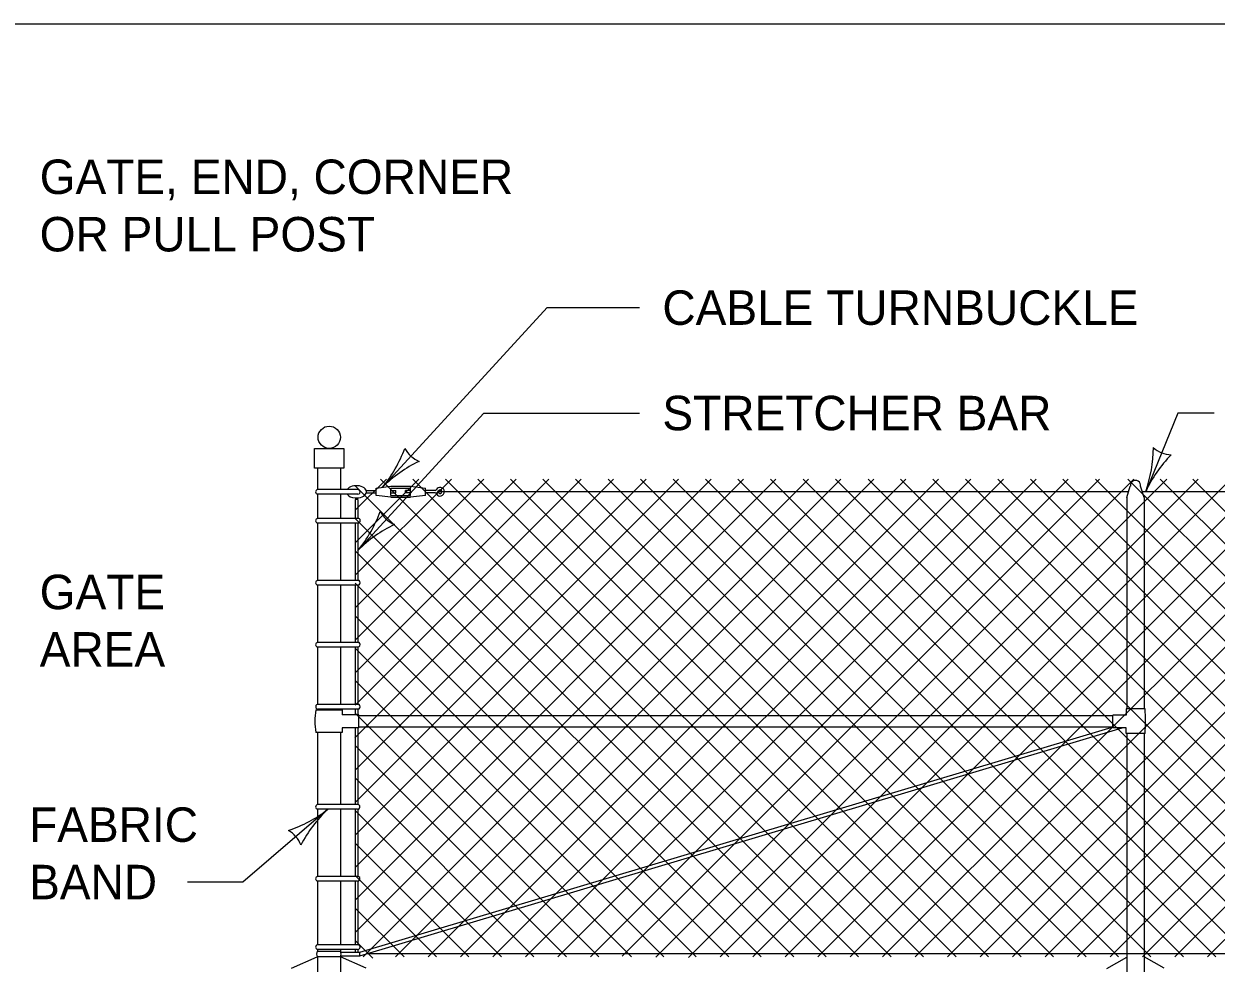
# Model space of a CAD drawing. Extents: x 49973.1 to 50021, y 49987.6 to 50015.4.
# Drawn here: x 50004.917 to 50006.994, y 49997.363 to 49998.999 of the extents above; entities that cross this region are included whole.
import ezdxf

# ---------------------------------------------------------------- set-up
doc = ezdxf.new("R2010")
doc.units = 0
for name, color, linetype in [('Level 1', 7, 'Continuous'), ('Level 2', 7, 'Continuous'), ('Level 3', 7, 'Continuous')]:
    doc.layers.add(name, color=color, linetype=linetype)

msp = doc.modelspace()

# ---------------------------------------------------------------- linework, layer by layer
at = {"layer": 'Level 1'}
for p, q in [((50005.4288, 49998.2252), (50005.4288, 49998.188)), ((50005.4688, 49998.2252), (50005.4688, 49998.188)), ((50005.9448, 49998.2062), (50005.4942, 49997.7556)), ((50005.5489, 49998.2062), (50005.4944, 49998.1518)), ((50005.6055, 49998.2062), (50005.4944, 49998.0952)), ((50005.6621, 49998.2062), (50005.4944, 49998.0386)), ((50005.7187, 49998.2062), (50005.4944, 49997.9819)), ((50005.8317, 49998.2062), (50005.4944, 49997.8689)), ((50005.7751, 49998.2062), (50005.4944, 49997.9255)), ((50005.8885, 49998.2062), (50005.4944, 49997.8124)), ((50006.2842, 49998.2062), (50005.4944, 49997.4164)), ((50006.1711, 49998.2062), (50005.4944, 49997.5295)), ((50006.1147, 49998.2062), (50005.4944, 49997.5859)), ((50006.058, 49998.2062), (50005.4944, 49997.6426)), ((50006.0015, 49998.2062), (50005.4944, 49997.6991)), ((50006.2276, 49998.2062), (50005.4944, 49997.473)), ((50006.3152, 49997.3739), (50005.4944, 49998.1947)), ((50006.3408, 49998.2062), (50005.5084, 49997.3738)), ((50005.531, 49998.1906), (50005.5568, 49998.1938)), ((50006.3716, 49997.3739), (50005.5389, 49998.2062)), ((50005.5568, 49998.1938), (50005.591, 49998.1938)), ((50006.3978, 49998.2062), (50005.565, 49997.3738)), ((50005.591, 49998.1938), (50005.6168, 49998.1906)), ((50006.4282, 49997.3739), (50005.5953, 49998.2062)), ((50006.454, 49998.2062), (50005.6216, 49997.3738)), ((50006.4848, 49997.3739), (50005.6521, 49998.2062)), ((50006.5104, 49998.2062), (50005.678, 49997.3738)), ((50006.5414, 49997.3739), (50005.7083, 49998.2062)), ((50006.567, 49998.2062), (50005.7346, 49997.3738)), ((50006.5978, 49997.3739), (50005.765, 49998.2062)), ((50006.624, 49998.2062), (50005.7912, 49997.3738)), ((50006.6544, 49997.3739), (50005.8217, 49998.2062)), ((50006.6806, 49998.2062), (50005.8478, 49997.3738)), ((50006.711, 49997.3739), (50005.8786, 49998.2062)), ((50006.7368, 49998.2062), (50005.9044, 49997.3738)), ((50006.7676, 49997.3739), (50005.935, 49998.2062)), ((50006.791, 49998.2062), (50005.9598, 49997.375)), ((50006.8242, 49997.3739), (50005.9917, 49998.2062)), ((50006.8511, 49998.2062), (50006.0181, 49997.3733)), ((50006.8808, 49997.3739), (50006.0484, 49998.2062)), ((50006.9085, 49998.2062), (50006.075, 49997.3728)), ((50006.9375, 49997.3738), (50006.1047, 49998.2062)), ((50006.9631, 49998.2062), (50006.1306, 49997.3738)), ((50006.9939, 49997.3738), (50006.1614, 49998.2062)), ((50007.0197, 49998.2062), (50006.1872, 49997.3738)), ((50007.0505, 49997.3738), (50006.218, 49998.2062)), ((50007.0763, 49998.2062), (50006.2438, 49997.3738)), ((50007.1071, 49997.3738), (50006.2747, 49998.2062)), ((50007.1329, 49998.2062), (50006.3004, 49997.3738)), ((50007.1637, 49997.3738), (50006.3313, 49998.2062)), ((50007.1895, 49998.2062), (50006.357, 49997.3738)), ((50007.2203, 49997.3738), (50006.3879, 49998.2062)), ((50007.2459, 49998.2062), (50006.4134, 49997.3738)), ((50007.2769, 49997.3738), (50006.4445, 49998.2062)), ((50007.3025, 49998.2062), (50006.47, 49997.3738)), ((50007.2938, 49997.4132), (50006.5009, 49998.2062)), ((50007.2938, 49997.4698), (50006.5575, 49998.2062)), ((50007.2938, 49997.5264), (50006.6141, 49998.2062)), ((50007.2938, 49997.583), (50006.6707, 49998.2062)), ((50007.2938, 49997.6396), (50006.7273, 49998.2062)), ((50007.2938, 49997.6962), (50006.7839, 49998.2062)), ((50006.8388, 49998.1741), (50006.8448, 49998.1939)), ((50007.2938, 49997.7528), (50006.8405, 49998.2062)), ((50006.8688, 49998.1741), (50006.8625, 49998.1936)), ((50007.2938, 49997.8092), (50006.8969, 49998.2062)), ((50007.2938, 49997.8658), (50006.9535, 49998.2062)), ((50005.4994, 49998.188), (50005.4288, 49998.188)), ((50005.4288, 49998.18), (50005.4288, 49998.1378)), ((50005.4994, 49998.1799), (50005.429, 49998.1799)), ((50005.4688, 49998.1799), (50005.4688, 49998.1378)), ((50005.4994, 49998.1704), (50005.4944, 49998.1704)), ((50005.4944, 49998.1704), (50005.4944, 49998.1509)), ((50005.4994, 49998.1704), (50005.4994, 49998.1378)), ((50005.514, 49998.1863), (50005.531, 49998.1863)), ((50005.514, 49998.1821), (50005.531, 49998.1821)), ((50005.531, 49998.1778), (50005.531, 49998.1906)), ((50005.5568, 49998.1746), (50005.531, 49998.1778)), ((50005.5568, 49998.1906), (50005.591, 49998.1906)), ((50005.5568, 49998.1778), (50005.5568, 49998.1906)), ((50005.5568, 49998.1863), (50005.5653, 49998.1863)), ((50005.5568, 49998.1821), (50005.5653, 49998.1821)), ((50005.5568, 49998.1778), (50005.591, 49998.1778)), ((50005.5568, 49998.1746), (50005.591, 49998.1746)), ((50005.5653, 49998.1821), (50005.5653, 49998.1863)), ((50005.5825, 49998.1821), (50005.5825, 49998.1863)), ((50005.591, 49998.1863), (50005.5825, 49998.1863)), ((50005.591, 49998.1821), (50005.5825, 49998.1821)), ((50005.591, 49998.1778), (50005.591, 49998.1906)), ((50005.6168, 49998.1778), (50005.591, 49998.1746)), ((50005.6168, 49998.1778), (50005.6168, 49998.1906)), ((50005.6339, 49998.1863), (50005.6168, 49998.1863)), ((50005.6339, 49998.1821), (50005.6168, 49998.1821)), ((50005.6398, 49998.1826), (50005.6361, 49998.1804)), ((50006.8418, 49998.1843), (50005.6416, 49998.1843)), ((50006.8388, 49998.1741), (50006.8388, 49997.8059)), ((50007.2954, 49998.1843), (50006.8655, 49998.1843)), ((50006.8688, 49998.1741), (50006.8688, 49997.8059)), ((50005.4944, 49998.1509), (50005.4944, 49998.1378)), ((50005.4993, 49998.1378), (50005.4288, 49998.1378)), ((50005.4288, 49998.1298), (50005.4288, 49998.0298)), ((50005.4997, 49998.1297), (50005.429, 49998.1297)), ((50005.4688, 49998.1297), (50005.4688, 49998.0298)), ((50006.2586, 49997.3739), (50005.4944, 49998.1378)), ((50005.4944, 49998.1297), (50005.4944, 49998.0298)), ((50005.4994, 49998.1297), (50005.4994, 49998.0298)), ((50007.2938, 49998.141), (50006.5266, 49997.3738)), ((50006.202, 49997.3739), (50005.4944, 49998.0812)), ((50007.2938, 49998.0843), (50006.5832, 49997.3738)), ((50005.4993, 49998.0298), (50005.4288, 49998.0298)), ((50006.1454, 49997.3739), (50005.4944, 49998.0247)), ((50007.2938, 49998.0277), (50006.6398, 49997.3738)), ((50005.4288, 49998.0218), (50005.4288, 49997.9218)), ((50005.4992, 49998.0217), (50005.429, 49998.0217)), ((50005.4688, 49998.0217), (50005.4688, 49997.9218)), ((50005.4944, 49998.0217), (50005.4944, 49997.9218)), ((50005.4994, 49998.0217), (50005.4994, 49997.9218)), ((50006.0888, 49997.3739), (50005.4944, 49997.968)), ((50007.2938, 49997.9711), (50006.6964, 49997.3738)), ((50005.4993, 49997.9218), (50005.4288, 49997.9218)), ((50005.4288, 49997.9138), (50005.4288, 49997.8138)), ((50005.4992, 49997.9137), (50005.429, 49997.9137)), ((50005.4688, 49997.9137), (50005.4688, 49997.8138)), ((50005.4944, 49997.9137), (50005.4944, 49997.8138)), ((50006.0322, 49997.3739), (50005.4944, 49997.9117)), ((50005.4994, 49997.9137), (50005.4994, 49997.8138)), ((50007.2938, 49997.9147), (50006.7528, 49997.3738)), ((50005.9758, 49997.3739), (50005.4944, 49997.8551)), ((50007.2938, 49997.8581), (50006.8094, 49997.3738)), ((50005.4993, 49997.8138), (50005.4285, 49997.8138)), ((50005.4288, 49997.8059), (50005.4288, 49997.804)), ((50005.4992, 49997.8057), (50005.4299, 49997.8057)), ((50005.4688, 49997.8057), (50005.4688, 49997.804)), ((50005.4944, 49997.8057), (50005.4944, 49997.7956)), ((50005.9192, 49997.3739), (50005.4944, 49997.7987)), ((50005.4994, 49997.8057), (50005.4994, 49997.7956)), ((50006.8704, 49997.8059), (50006.8376, 49997.8059)), ((50006.8376, 49997.8059), (50006.8376, 49997.7951)), ((50007.2938, 49997.8015), (50006.866, 49997.3738)), ((50005.5009, 49997.7956), (50005.472, 49997.7956)), ((50005.5009, 49997.7727), (50005.5009, 49997.7956)), ((50006.8144, 49997.7941), (50005.5009, 49997.7941)), ((50006.8376, 49997.7951), (50006.8144, 49997.7951)), ((50006.8144, 49997.773), (50006.8144, 49997.7951)), ((50005.4288, 49997.765), (50005.4288, 49997.6391)), ((50005.4688, 49997.765), (50005.4688, 49997.6391)), ((50005.5009, 49997.7727), (50005.472, 49997.7727)), ((50005.4944, 49997.7727), (50005.4944, 49997.6391)), ((50005.4994, 49997.7727), (50005.4994, 49997.6391)), ((50006.8144, 49997.7741), (50005.5009, 49997.7741)), ((50005.5029, 49997.382), (50006.8132, 49997.7741)), ((50005.5029, 49997.3756), (50006.8308, 49997.773)), ((50006.8374, 49997.773), (50006.8144, 49997.773)), ((50006.8374, 49997.7633), (50006.8374, 49997.773)), ((50006.8704, 49997.7633), (50006.8374, 49997.7633)), ((50006.8388, 49997.7633), (50006.8388, 49997.3739)), ((50006.8688, 49997.7633), (50006.8688, 49997.3739)), ((50005.8626, 49997.3739), (50005.4944, 49997.7421)), ((50007.2938, 49997.7449), (50006.9226, 49997.3738)), ((50005.806, 49997.3739), (50005.4944, 49997.6856)), ((50007.2938, 49997.6884), (50006.9792, 49997.3738)), ((50005.4991, 49997.6391), (50005.4288, 49997.6391)), ((50005.4288, 49997.6311), (50005.4288, 49997.5141)), ((50005.4987, 49997.631), (50005.429, 49997.631)), ((50005.4688, 49997.631), (50005.4688, 49997.5141)), ((50005.4944, 49997.631), (50005.4944, 49997.5271)), ((50005.4994, 49997.631), (50005.4994, 49997.5141)), ((50005.7494, 49997.3739), (50005.4944, 49997.629)), ((50005.6928, 49997.3739), (50005.4944, 49997.5723)), ((50005.4944, 49997.5271), (50005.4944, 49997.5141)), ((50005.4991, 49997.5141), (50005.4288, 49997.5141)), ((50005.4288, 49997.5061), (50005.4288, 49997.395)), ((50005.4987, 49997.506), (50005.429, 49997.506)), ((50005.4688, 49997.506), (50005.4688, 49997.395)), ((50005.4944, 49997.506), (50005.4944, 49997.395)), ((50005.6364, 49997.3739), (50005.4951, 49997.5152)), ((50005.4994, 49997.506), (50005.4994, 49997.395)), ((50005.5798, 49997.3739), (50005.4948, 49997.4589)), ((50005.5252, 49997.3719), (50005.4944, 49997.4027)), ((50005.4689, 49997.3836), (50005.4285, 49997.3836)), ((50005.499, 49997.395), (50005.4287, 49997.395)), ((50005.4288, 49997.387), (50005.4288, 49997.3836)), ((50005.4989, 49997.3869), (50005.4289, 49997.3869)), ((50005.4688, 49997.3869), (50005.4688, 49997.3836)), ((50005.4697, 49997.382), (50005.5029, 49997.382)), ((50005.4944, 49997.3869), (50005.4944, 49997.382)), ((50005.4994, 49997.3869), (50005.4994, 49997.382)), ((50005.5029, 49997.3756), (50005.5029, 49997.382)), ((50005.3838, 49997.3541), (50005.4285, 49997.3741)), ((50005.4689, 49997.3741), (50005.4285, 49997.3741)), ((50005.4288, 49997.3741), (50005.4288, 49996.9341)), ((50005.4688, 49997.3741), (50005.4688, 49996.9341)), ((50005.5138, 49997.3541), (50005.4689, 49997.3741)), ((50005.4696, 49997.3756), (50005.5029, 49997.3756)), ((50007.29, 49997.3794), (50005.5156, 49997.3794)), ((50006.8038, 49997.354), (50006.8388, 49997.3735)), ((50006.8388, 49997.3739), (50006.8388, 49996.9341)), ((50006.8688, 49997.3739), (50006.8688, 49996.9341)), ((50006.9038, 49997.3541), (50006.8688, 49997.3738))]:
    msp.add_line(p, q, dxfattribs=at)
for points in [[(49999.3835, 49998.9992), (50016.7501, 49998.9992), (50016.7501, 49987.7988), (49999.3835, 49987.7988)], [(50005.4747, 49998.2595), (50005.4747, 49998.2252), (50005.4238, 49998.2252), (50005.4238, 49998.2595)]]:
    msp.add_lwpolyline(points, close=True, dxfattribs=at)
for points in [[(50005.4261, 49997.804), (50005.472, 49997.804), (50005.472, 49997.7956)], [(50005.472, 49997.7727), (50005.472, 49997.765), (50005.4261, 49997.765)]]:
    msp.add_lwpolyline(points, dxfattribs=at)
msp.add_circle((50005.4494, 49998.2791), 0.0194, dxfattribs=at)
for centre, radius, start, end in [((50005.6425, 49998.1842), 0.00749, 210.935, 153.6122), ((50006.8537, 49998.1951), 0.00895, 350.428, 187.6246), ((50005.4299, 49998.184), 0.00417, 104.8473, 257.4184), ((50005.4994, 49998.184), 0.00405, 269.3348, 90.4595), ((50005.6339, 49998.1885), 0.00214, 270, 333.6122), ((50005.6339, 49998.1885), 0.00642, 270, 333.6122), ((50005.6425, 49998.1842), 0.00321, 210.2657, 153.6122), ((50005.4299, 49998.1338), 0.00417, 104.8473, 257.4184), ((50005.4994, 49998.1338), 0.00405, 273.176, 92.0788), ((50005.4299, 49998.0258), 0.00417, 104.8473, 257.4184), ((50005.4994, 49998.0258), 0.00405, 266.824, 92.0788), ((50005.4299, 49997.9178), 0.00417, 104.8473, 257.4184), ((50005.4994, 49997.9178), 0.00405, 270.7491, 92.0788), ((50005.4994, 49997.9178), 0.00405, 266.824, 270.7491), ((50005.5306, 49997.7845), 0.1063, 169.4297, 190.5658), ((50005.4299, 49997.8099), 0.00417, 109.5021, 270.4471), ((50005.4994, 49997.8098), 0.00405, 266.824, 92.0788), ((50006.6192, 49997.7846), 0.2521, 355.155, 4.8478), ((50005.4299, 49997.6351), 0.00417, 104.8473, 257.4184), ((50005.4989, 49997.6351), 0.00405, 266.824, 87.9212), ((50005.4299, 49997.5101), 0.00417, 104.8473, 257.4184), ((50005.4989, 49997.5101), 0.00405, 266.824, 87.9212), ((50005.4298, 49997.391), 0.00417, 104.8473, 257.4184), ((50005.4372, 49997.3789), 0.00992, 151.3522, 208.5571), ((50005.4609, 49997.3789), 0.00931, 329.2674, 30.6196), ((50005.4991, 49997.391), 0.00405, 266.824, 92.0788)]:
    msp.add_arc(centre, radius, start, end, dxfattribs=at)
for start_param, end_param in [(4.569027, 9.026485), (3.521347, 4.569027), (4.855848, 4.855848)]:
    msp.add_ellipse((50005.4968, 49998.184), major_axis=(0.0175, 0.0001), ratio=0.610393, start_param=start_param, end_param=end_param, dxfattribs=at)
at = {"layer": 'Level 3'}
for p, q in [((50005.5424, 49998.1919), (50005.829, 49998.5049)), ((50005.829, 49998.5049), (50005.9897, 49998.5049)), ((50005.4994, 49998.0821), (50005.7186, 49998.3213)), ((50005.7186, 49998.3213), (50005.9897, 49998.3213)), ((50006.9278, 49998.3213), (50006.8716, 49998.1843)), ((50006.9909, 49998.3213), (50006.9278, 49998.3213)), ((50005.447, 49997.631), (50005.2991, 49997.5043)), ((50005.2991, 49997.5043), (50005.2024, 49997.5043))]:
    msp.add_line(p, q, dxfattribs=at)
for centre, radius, start, end in [((50005.3623, 49998.34), 0.233, 320.5807, 339.8305), ((50005.6285, 49998.2869), 0.0548, 209.8922, 245.6145), ((50006.6519, 49998.262), 0.233, 340.529, 359.7789), ((50006.9202, 49998.3029), 0.0548, 229.8405, 265.5629), ((50005.7006, 49998.0359), 0.2223, 115.2094, 135.3929), ((50007.0736, 49998.0916), 0.2223, 135.1577, 155.3412), ((50005.3194, 49998.23), 0.233, 320.5807, 339.8305), ((50005.5856, 49998.177), 0.0548, 209.8922, 245.6145), ((50005.6577, 49997.9259), 0.2223, 115.2094, 135.3929), ((50005.3095, 49997.8057), 0.2223, 288.0156, 308.1991), ((50005.607, 49997.4617), 0.233, 133.3869, 152.6368), ((50005.3496, 49997.5477), 0.0548, 22.6984, 58.4208)]:
    msp.add_arc(centre, radius, start, end, dxfattribs=at)

# ---------------------------------------------------------------- texts
at = {"layer": 'Level 2'}
for s, p in [('GATE, END, CORNER', (50004.9451, 49998.7028)), ('OR PULL POST', (50004.9451, 49998.6028)), ('CABLE TURNBUCKLE', (50006.0297, 49998.4749)), ('STRETCHER BAR', (50006.0297, 49998.2913)), ('GATE', (50004.9451, 49997.9796)), ('AREA', (50004.9451, 49997.8796)), ('FABRIC', (50004.9266, 49997.5743)), ('BAND', (50004.9266, 49997.4743))]:
    msp.add_text(s, height=0.06, dxfattribs=at).set_placement(p)

doc.saveas('drawing.dxf')
